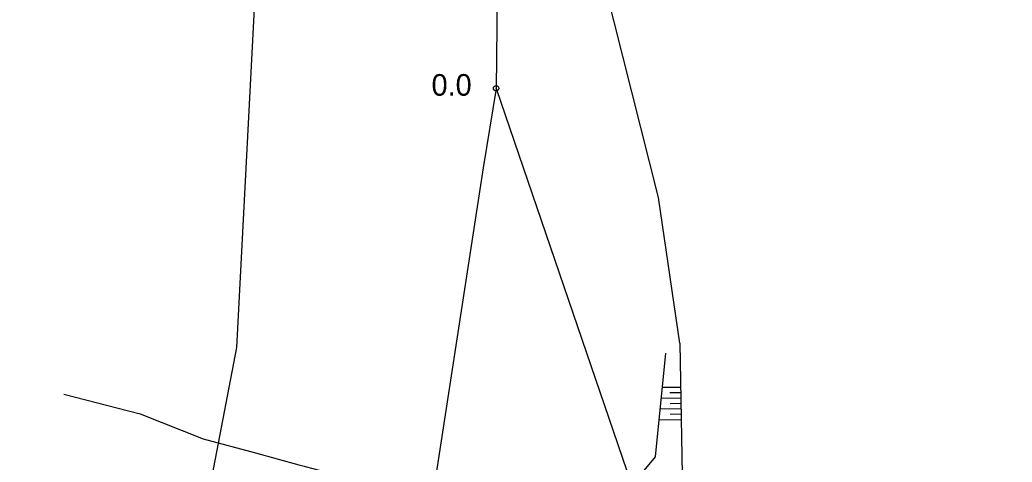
# Model space of a CAD drawing. Extents: x -737422 to -734235, y -1145631 to -1142623.
# Drawn here: x -735091.9 to -735000, y -1143022.4 to -1142981.5 of the extents above; entities that cross this region are included whole.
import ezdxf

# ---------------------------------------------------------------- set-up
doc = ezdxf.new("R2010")
doc.units = 0
for name, color, linetype in [('Vrstva 1', 7, 'Continuous'), ('Vrstva 2', 7, 'Continuous'), ('Vrstva 20', 7, 'Continuous'), ('Vrstva 21', 7, 'Continuous'), ('Vrstva 3', 7, 'Continuous'), ('Vrstva 6', 7, 'Continuous'), ('Vrstva 7', 7, 'Continuous'), ('Vrstva 8', 7, 'Continuous')]:
    doc.layers.add(name, color=color, linetype=linetype)

# ---------------------------------------------------------------- blocks, each defined once
blk = doc.blocks.new('5.200')
at = {"layer": 'Vrstva 1'}
for radius in [0.5, 0.01]:
    blk.add_circle((0, 0), radius, dxfattribs=at)

msp = doc.modelspace()

# ---------------------------------------------------------------- linework, layer by layer
at = {"layer": 'Vrstva 2'}
for points in [[(-735014.111, -1142804.316), (-735027.1, -1142858.49), (-735039.95, -1142908.87), (-735047.15, -1142946.91), (-735047.51, -1142956.15), (-735047.84, -1142987.81), (-735049.04, -1142995.17), (-735054.73, -1143032.1), (-735062.19, -1143054.47)], [(-735047.84, -1142987.81), (-735035.74, -1143023.25), (-735035.52, -1143024.84), (-735035.34, -1143033.99), (-735035.46, -1143039.98), (-735036.11, -1143057.68), (-735035.82, -1143061.77), (-735035.37, -1143063.8), (-735034.62, -1143065.72), (-735027.19, -1143079.99), (-735026.74, -1143080.64), (-735026.77, -1143080.92), (-735029.28, -1143083.32), (-735034.74, -1143087.91), (-735037.38, -1143090.19), (-735037.41, -1143090.46), (-735036.99, -1143091.1)]]:
    msp.add_lwpolyline(points, dxfattribs=at)
at = {"layer": 'Vrstva 20'}
for points in [[(-735030.83, -1143011.41), (-735030.55, -1143027.1)], [(-735032.15, -1143012.33), (-735033.11, -1143021.94)], [(-735033.11, -1143021.94), (-735035.52, -1143024.84)]]:
    msp.add_lwpolyline(points, dxfattribs=at)
at = {"layer": 'Vrstva 21'}
for points in [[(-735030.76, -1143015.51), (-735032.47, -1143015.54)], [(-735030.75, -1143016.01), (-735031.75, -1143016.03)], [(-735030.74, -1143016.51), (-735032.57, -1143016.54)], [(-735030.73, -1143017.01), (-735031.73, -1143017.03)], [(-735030.72, -1143017.51), (-735032.67, -1143017.54)], [(-735030.71, -1143018.01), (-735031.71, -1143018.03)], [(-735030.7, -1143018.51), (-735032.77, -1143018.55)]]:
    msp.add_lwpolyline(points, dxfattribs=at)
at = {"layer": 'Vrstva 3'}
for points in [[(-735030.83, -1143011.41), (-735032.8, -1142997.91), (-735039.4, -1142971.69), (-735037.12, -1142942.87), (-735030.85, -1142908.9), (-735026, -1142888.07), (-735015.45, -1142858.1), (-735006.84, -1142828.99), (-735003.23, -1142812.13), (-735000.048, -1142802.119)], [(-735034.121, -1142807.443), (-735041.41, -1142833.15), (-735049.67, -1142873.94), (-735063.61, -1142929.72), (-735068.77, -1142951.92), (-735071.87, -1143011.83), (-735079.1, -1143049.53), (-735090.46, -1143071.74), (-735105.06, -1143095.74), (-735128.12, -1143122.71), (-735156.5, -1143145.42), (-735208.29, -1143180.56), (-735229.22, -1143198.3), (-735243.77, -1143211.78), (-735256.18, -1143225.98), (-735267.54, -1143251.18), (-735270.892, -1143271.893)], [(-735030.83, -1143011.41), (-735030.55, -1143027.1)]]:
    msp.add_lwpolyline(points, dxfattribs=at)
at = {"layer": 'Vrstva 8'}
msp.add_lwpolyline([(-735087.87, -1143016.15), (-735080.82, -1143017.98), (-735074.96, -1143020.27), (-735070.11, -1143021.59), (-735066.12, -1143022.68), (-735065.62, -1143022.82), (-735065.54, -1143022.84), (-735064.12, -1143023.23), (-735059.15, -1143024.58), (-735055.53, -1143025.57), (-735051.72, -1143026.61), (-735047.69, -1143027.71), (-735046.67, -1143027.99), (-735045.91, -1143028.19), (-735043.84, -1143028.76), (-735032.07, -1143030.74)], dxfattribs=at)

# ---------------------------------------------------------------- block references
at = {"layer": 'Vrstva 6', "xscale": 0.5, "yscale": 0.5}
msp.add_blockref('5.200', (-735047.84, -1142987.81), dxfattribs=at)

# ---------------------------------------------------------------- texts
at = {"layer": 'Vrstva 7'}
msp.add_text('0.0', height=2, dxfattribs=at).set_placement((-735053.82, -1142988.49))

doc.saveas('drawing.dxf')
